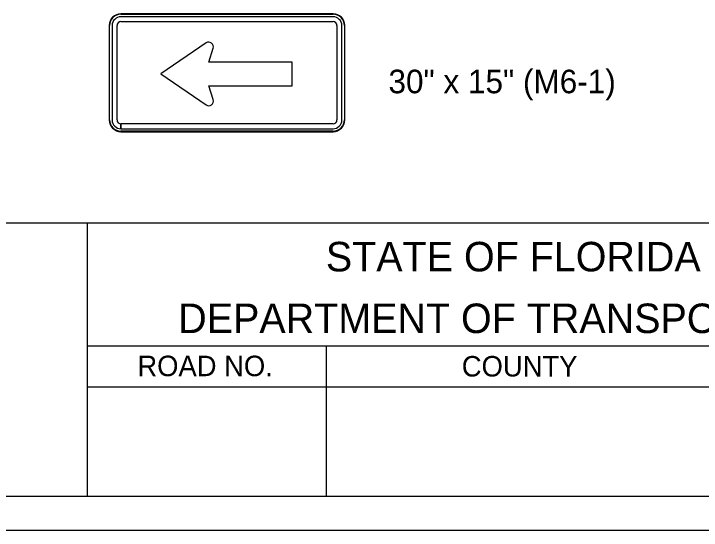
# Model space of a CAD drawing. Extents: x 17890587 to 17890754, y 17897693 to 17897992.
# Drawn here: x 17890611.5 to 17890617.41, y 17897873.1 to 17897877.54 of the extents above; entities that cross this region are included whole.
import ezdxf

# ---------------------------------------------------------------- set-up
doc = ezdxf.new("R2010")
doc.units = 0
for name, color, linetype in [('GSBWFill', 7, 'Continuous'), ('GSColorFill', 7, 'Continuous'), ('GSOutline', 7, 'Continuous'), ('PlotBorder_dp', 7, 'Continuous'), ('SheetBorder_dp', 7, 'Continuous'), ('SheetLines_dp', 7, 'Continuous'), ('TextMisc', 7, 'Continuous')]:
    doc.layers.add(name, color=color, linetype=linetype)

msp = doc.modelspace()

# ---------------------------------------------------------------- linework, layer by layer
at = {"layer": 'GSBWFill'}
for points in [[(17890613.1559, 17897877.2887), (17890612.7678, 17897877.0225), (17890613.1559, 17897876.7562)], [(17890613.2174, 17897876.8019), (17890613.1795, 17897876.9213), (17890613.8958, 17897876.9213), (17890613.8958, 17897877.1237), (17890613.1795, 17897877.1237), (17890613.2174, 17897877.2431)]]:
    msp.add_lwpolyline(points, dxfattribs=at)
for centre, major_axis, start_param, end_param in [((17890613.1788, 17897877.2553), (0.0405, 0), 5.975991, 8.455234), ((17890613.1788, 17897876.7896), (-0.0405, 0), 0.969544, 3.448787)]:
    msp.add_ellipse(centre, major_axis=major_axis, ratio=0.999949, start_param=start_param, end_param=end_param, dxfattribs=at)
at = {"layer": 'GSColorFill'}
for p, q in [((17890614.2466, 17897877.5392), (17890612.4243, 17897877.5392)), ((17890614.2466, 17897877.5392), (17890612.4243, 17897877.5392)), ((17890612.4243, 17897877.535), (17890614.2466, 17897877.535)), ((17890614.2466, 17897877.5139), (17890612.4243, 17897877.5139)), ((17890612.4243, 17897877.4717), (17890614.2466, 17897877.4717)), ((17890612.323, 17897877.4379), (17890612.323, 17897876.628)), ((17890612.323, 17897877.4379), (17890612.323, 17897876.628)), ((17890612.3273, 17897876.628), (17890612.3273, 17897877.4379)), ((17890612.3483, 17897877.4379), (17890612.3483, 17897876.628)), ((17890612.3905, 17897876.628), (17890612.3905, 17897877.4379)), ((17890614.2803, 17897877.4379), (17890614.2803, 17897876.628)), ((17890614.3225, 17897876.628), (17890614.3225, 17897877.4379)), ((17890614.3436, 17897877.4379), (17890614.3436, 17897876.628)), ((17890614.3478, 17897876.628), (17890614.3478, 17897877.4379)), ((17890614.3478, 17897876.628), (17890614.3478, 17897877.4379)), ((17890612.4243, 17897876.5521), (17890612.4243, 17897876.5943)), ((17890614.2466, 17897876.5943), (17890612.4247, 17897876.5943)), ((17890612.4247, 17897876.5943), (17890612.4247, 17897876.5521)), ((17890612.4243, 17897876.5268), (17890612.4243, 17897876.531)), ((17890614.2466, 17897876.531), (17890612.4243, 17897876.531)), ((17890612.4243, 17897876.531), (17890612.4243, 17897876.5268)), ((17890612.4243, 17897876.5268), (17890614.2466, 17897876.5268)), ((17890612.4243, 17897876.5268), (17890614.2466, 17897876.5268)), ((17890612.4247, 17897876.5521), (17890614.2466, 17897876.5521))]:
    msp.add_line(p, q, dxfattribs=at)
for points in [[(17890613.1559, 17897877.2887), (17890612.7678, 17897877.0225), (17890613.1559, 17897876.7562)], [(17890613.2174, 17897876.8019), (17890613.1795, 17897876.9213), (17890613.8958, 17897876.9213), (17890613.8958, 17897877.1237), (17890613.1795, 17897877.1237), (17890613.2174, 17897877.2431)]]:
    msp.add_lwpolyline(points, dxfattribs=at)
for centre, radius, start, end in [((17890612.4243, 17897877.4379), 0.1012, 90, 180), ((17890612.4243, 17897877.4379), 0.1012, 90, 180), ((17890612.4243, 17897877.4379), 0.097, 90, 180), ((17890612.4243, 17897877.4379), 0.0759, 90, 180), ((17890614.2466, 17897877.4379), 0.1012, 0, 90), ((17890614.2466, 17897877.4379), 0.1012, 0, 90), ((17890614.2466, 17897877.4379), 0.097, 0, 90), ((17890614.2466, 17897877.4379), 0.0759, 0, 90), ((17890612.4243, 17897877.4379), 0.0337, 90, 180), ((17890614.2466, 17897877.4379), 0.0337, 0, 90), ((17890612.4243, 17897876.628), 0.1012, 180, 270), ((17890612.4243, 17897876.628), 0.1012, 180, 270), ((17890612.4243, 17897876.628), 0.097, 180, 270), ((17890612.4243, 17897876.628), 0.0759, 180, 270), ((17890612.4243, 17897876.628), 0.0337, 180, 270), ((17890614.2466, 17897876.628), 0.1012, 270, 0), ((17890614.2466, 17897876.628), 0.1012, 270, 0), ((17890614.2466, 17897876.628), 0.097, 270, 0), ((17890614.2466, 17897876.628), 0.0759, 270, 0), ((17890614.2466, 17897876.628), 0.0337, 270, 0)]:
    msp.add_arc(centre, radius, start, end, dxfattribs=at)
for centre, major_axis, start_param, end_param in [((17890613.1788, 17897877.2553), (0.0405, 0), 5.975991, 8.455234), ((17890613.1788, 17897876.7896), (-0.0405, 0), 0.969544, 3.448787)]:
    msp.add_ellipse(centre, major_axis=major_axis, ratio=0.999949, start_param=start_param, end_param=end_param, dxfattribs=at)
at = {"layer": 'GSOutline'}
for points in [[(17890613.1559, 17897877.2887), (17890612.7678, 17897877.0225), (17890613.1559, 17897876.7562)], [(17890613.2174, 17897876.8019), (17890613.1795, 17897876.9213), (17890613.8958, 17897876.9213), (17890613.8958, 17897877.1237), (17890613.1795, 17897877.1237), (17890613.2174, 17897877.2431)]]:
    msp.add_lwpolyline(points, dxfattribs=at)
for centre, major_axis, start_param, end_param in [((17890613.1788, 17897877.2553), (0.0405, 0), 5.975991, 8.455234), ((17890613.1788, 17897876.7896), (-0.0405, 0), 0.969544, 3.448787)]:
    msp.add_ellipse(centre, major_axis=major_axis, ratio=0.999949, start_param=start_param, end_param=end_param, dxfattribs=at)
at = {"layer": 'PlotBorder_dp'}
msp.add_lwpolyline([(17890586.7562, 17897873.1039), (17890635.165, 17897873.1039), (17890635.165, 17897904.2029), (17890586.7562, 17897904.2029)], close=True, dxfattribs=at)
at = {"layer": 'SheetBorder_dp'}
for p, q in [((17890588.3699, 17897875.7444), (17890633.5514, 17897875.7444)), ((17890588.3699, 17897873.3973), (17890633.5514, 17897873.3973))]:
    msp.add_line(p, q, dxfattribs=at)
at = {"layer": 'SheetLines_dp'}
for p, q in [((17890612.1342, 17897875.7444), (17890612.1342, 17897873.3973)), ((17890612.1342, 17897874.6882), (17890620.9358, 17897874.6882)), ((17890614.1879, 17897874.6882), (17890614.1879, 17897873.3973)), ((17890612.1342, 17897874.3361), (17890620.9358, 17897874.3361))]:
    msp.add_line(p, q, dxfattribs=at)

# ---------------------------------------------------------------- texts
at = {"layer": 'TextMisc'}
for s, height, p in [('30" x 15" (M6-1)', 0.202479, (17890614.7226, 17897876.8567)), ('STATE OF FLORIDA', 0.253486, (17890614.1847, 17897875.3269)), ('DEPARTMENT OF TRANSPORTATION', 0.253486, (17890612.9166, 17897874.7972)), ('ROAD NO.', 0.17603, (17890612.5654, 17897874.4271)), ('COUNTY', 0.17603, (17890615.3526, 17897874.4242))]:
    msp.add_text(s, height=height, dxfattribs=at).set_placement(p)

doc.saveas('drawing.dxf')
